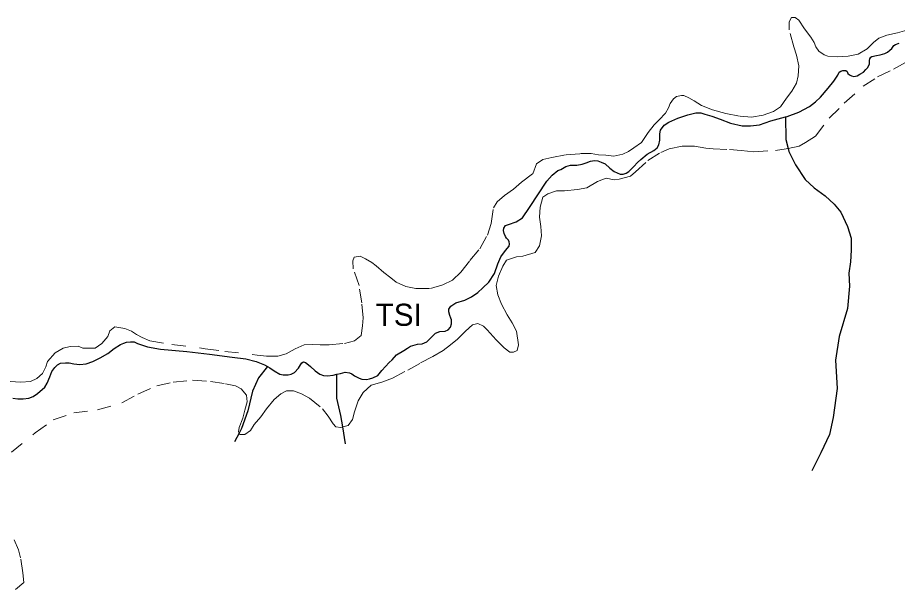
# Model space of a CAD drawing. Extents: x 391.8 to 446, y 8452 to 8507.5.
# Drawn here: x 420.22 to 426.58, y 8476.91 to 8481.04 of the extents above; entities that cross this region are included whole.
import ezdxf
from ezdxf.enums import TextEntityAlignment as Align

# ---------------------------------------------------------------- set-up
doc = ezdxf.new("R2010")
doc.units = 0
doc.header["$LTSCALE"] = 0.064
doc.linetypes.add('LONG_DASHED', pattern=[7.5, 6, -1.5])
doc.linetypes.add('SHORT_DASHED', pattern=[2.7, 1.5, -1.2])
for name, color, linetype, lineweight in [('21', 7, 'SHORT_DASHED', 13), ('63', 7, 'Continuous', 13), ('7', 7, 'Continuous', 25)]:
    doc.layers.add(name, color=color, linetype=linetype, lineweight=lineweight)
doc.layers.add('61', color=7, linetype='Continuous')

msp = doc.modelspace()

# ---------------------------------------------------------------- linework, layer by layer
at = {"layer": '21'}
for points in [[(420.9981, 8478.7971), (421.0479, 8478.7779), (421.0824, 8478.7549), (421.1246, 8478.732), (421.1783, 8478.709), (421.3393, 8478.6822), (421.5788, 8478.6516), (421.7206, 8478.6325), (421.9545, 8478.6057), (422.0235, 8478.598), (422.104, 8478.598), (422.1653, 8478.6133), (422.2305, 8478.6516), (422.2956, 8478.6784), (422.357, 8478.6822), (422.4106, 8478.6784), (422.4758, 8478.6784), (422.587, 8478.6899), (422.6598, 8478.709), (422.7058, 8478.7473), (422.7173, 8478.8162), (422.7211, 8478.8736), (422.7109, 8478.9827), (422.6918, 8479.1091), (422.6496, 8479.2277), (422.6458, 8479.2852), (422.6573, 8479.312), (422.6994, 8479.3196), (422.7378, 8479.3005), (422.7838, 8479.2737), (422.8144, 8479.2507), (422.8719, 8479.2009), (422.9218, 8479.1627), (422.9601, 8479.132), (423.0291, 8479.1014), (423.1019, 8479.0861), (423.2093, 8479.0861), (423.2974, 8479.1129), (423.3664, 8479.1473), (423.4277, 8479.2048), (423.4929, 8479.289), (423.5657, 8479.3732), (423.6194, 8479.4728), (423.6462, 8479.557), (423.6632, 8479.67), (423.69, 8479.7121), (423.7437, 8479.7581), (423.8088, 8479.804), (423.8663, 8479.8538), (423.9468, 8479.915), (423.9737, 8479.9878), (424.0197, 8480.0184), (424.0848, 8480.0337), (424.1883, 8480.0529), (424.2918, 8480.0605), (424.3685, 8480.0605), (424.4221, 8480.0529), (424.4758, 8480.049), (424.5333, 8480.0414), (424.5985, 8480.0567), (424.6406, 8480.0758), (424.679, 8480.1026), (424.7326, 8480.1409), (424.7825, 8480.2137), (424.8261, 8480.2693), (424.8606, 8480.3038), (424.9066, 8480.3536), (424.9296, 8480.3919), (424.9411, 8480.4225), (424.9641, 8480.4569), (424.9871, 8480.4722), (425.0216, 8480.4799), (425.0407, 8480.4799), (425.0752, 8480.4646), (425.1136, 8480.4416), (425.1672, 8480.4072), (425.2477, 8480.3765), (425.3436, 8480.3497), (425.4471, 8480.3306), (425.5276, 8480.3229), (425.6119, 8480.3383), (425.6886, 8480.3651), (425.7384, 8480.3995), (425.7806, 8480.4608), (425.8205, 8480.5111), (425.855, 8480.5685), (425.8665, 8480.6221), (425.8703, 8480.6949), (425.855, 8480.7714), (425.8358, 8480.8327), (425.8013, 8480.9552), (425.8013, 8481.0126), (425.8167, 8481.0432), (425.8435, 8481.0432), (425.8703, 8481.0241)], [(425.8703, 8481.0241), (425.9125, 8480.9628), (425.9585, 8480.9016), (425.9815, 8480.8633), (425.993, 8480.8327), (426.016, 8480.802), (426.0543, 8480.7752)], [(426.0543, 8480.7752), (426.0812, 8480.7638), (426.1501, 8480.7599), (426.2268, 8480.7638), (426.2996, 8480.7791), (426.3648, 8480.8174), (426.4108, 8480.8633), (426.4491, 8480.8939), (426.5066, 8480.9169), (426.5833, 8480.9322), (426.6523, 8480.9513)], [(425.9922, 8480.1878), (426.0907, 8480.3172), (426.1996, 8480.4259), (426.3369, 8480.5473), (426.4406, 8480.6146), (426.5546, 8480.6715), (426.6687, 8480.7336)], [(425.7933, 8480.0976), (425.873, 8480.1153), (425.9196, 8480.1412), (425.9922, 8480.1878)], [(422.5736, 8478.0861), (422.613, 8478.0979), (422.6441, 8478.1393), (422.6596, 8478.1963), (422.6856, 8478.274), (422.7218, 8478.3361), (422.7789, 8478.3878), (422.8566, 8478.4086), (422.9344, 8478.4396), (423.0432, 8478.4966), (423.1365, 8478.5483), (423.2247, 8478.5949), (423.3005, 8478.6376), (423.3523, 8478.6791), (423.4042, 8478.7205), (423.4612, 8478.7774), (423.513, 8478.824), (423.5493, 8478.8344), (423.5908, 8478.8137), (423.6167, 8478.7878), (423.6841, 8478.7153), (423.7411, 8478.6583), (423.7826, 8478.6273), (423.8085, 8478.6273), (423.8344, 8478.6376), (423.8448, 8478.6791), (423.8293, 8478.7774), (423.7982, 8478.8395), (423.7619, 8478.8965), (423.7204, 8478.9741), (423.6945, 8479.0414), (423.6841, 8479.1088), (423.6997, 8479.1761), (423.7308, 8479.2485), (423.7567, 8479.2899), (423.8293, 8479.3158), (423.8759, 8479.321), (423.964, 8479.3469), (423.9951, 8479.3935), (424.0107, 8479.466), (424.0055, 8479.5333), (423.9951, 8479.6006), (424.0003, 8479.673), (424.0211, 8479.7455), (424.0573, 8479.7714), (424.1195, 8479.7921), (424.1766, 8479.7921), (424.2699, 8479.8025), (424.3373, 8479.8128), (424.415, 8479.8594), (424.4785, 8479.8823), (424.5356, 8479.872), (424.5718, 8479.8772), (424.6548, 8479.8979), (424.6911, 8479.9289), (424.7792, 8480.0118), (424.8725, 8480.0687), (424.9347, 8480.0946), (425.028, 8480.1153), (425.1161, 8480.1153), (425.1991, 8480.0998), (425.2509, 8480.0946), (425.3702, 8480.0894), (425.4531, 8480.0843), (425.5464, 8480.0739)], [(425.5464, 8480.0739), (425.7019, 8480.0843), (425.7797, 8480.0946), (425.7933, 8480.0976)], [(420.7834, 8478.6554), (420.8333, 8478.6899), (420.8754, 8478.7396), (420.8908, 8478.7817), (420.9253, 8478.8085), (420.9559, 8478.8047), (420.9981, 8478.7971)], [(420.1701, 8478.4142), (420.2468, 8478.4104), (420.3158, 8478.4142), (420.3618, 8478.4372), (420.4039, 8478.4717), (420.4269, 8478.5214), (420.4384, 8478.5597), (420.4959, 8478.621), (420.5534, 8478.6554), (420.6033, 8478.6669), (420.6608, 8478.6707), (420.6953, 8478.6554), (420.7834, 8478.6554)], [(421.2289, 8478.3827), (421.3481, 8478.4086), (421.4881, 8478.4241), (421.6177, 8478.4137), (421.7266, 8478.3982), (421.7991, 8478.3827), (421.8406, 8478.362), (421.8769, 8478.3154), (421.8821, 8478.2688), (421.8665, 8478.2067), (421.851, 8478.1497), (421.825, 8478.0824), (421.8199, 8478.0513), (421.8244, 8478.0422)], [(420.3502, 8478.0436), (420.4798, 8478.1368), (420.6301, 8478.1886), (420.8012, 8478.2093), (420.9774, 8478.2611), (421.0915, 8478.3232), (421.2289, 8478.3827)], [(421.8244, 8478.0422), (421.8302, 8478.0306), (421.8665, 8478.0306), (421.908, 8478.0617), (421.9339, 8478.1031), (421.9806, 8478.1601), (422.022, 8478.217), (422.079, 8478.2843), (422.1257, 8478.3257), (422.1672, 8478.3464), (422.219, 8478.3464), (422.276, 8478.3257), (422.3331, 8478.2947), (422.4264, 8478.217), (422.4678, 8478.1652), (422.5041, 8478.1083), (422.5249, 8478.0876), (422.5611, 8478.0824), (422.5736, 8478.0861)], [(420.1791, 8477.9039), (420.3502, 8478.0436)], [(420.2086, 8476.9129), (420.2675, 8476.9622), (420.2604, 8477.032), (420.2449, 8477.1407), (420.2293, 8477.1976), (420.1982, 8477.2701)]]:
    msp.add_lwpolyline(points, dxfattribs=at)
at = {"layer": '63', "linetype": 'LONG_DASHED', "lineweight": 25}
for points in [[(425.7733, 8480.3259), (425.777, 8480.1624), (425.7933, 8480.0976)], [(425.7933, 8480.0976), (425.7985, 8480.0767), (425.8468, 8479.9802), (425.9165, 8479.873), (425.9809, 8479.8141), (426.0614, 8479.7552), (426.1258, 8479.6962), (426.1741, 8479.6373), (426.2224, 8479.5354), (426.2492, 8479.4497), (426.2492, 8479.364), (426.2438, 8479.2782), (426.2331, 8479.1978), (426.2381, 8479.1039), (426.222, 8478.9431), (426.163, 8478.7395), (426.1361, 8478.568), (426.1469, 8478.3644), (426.12, 8478.1554), (426.0932, 8478.0321), (426.0288, 8477.8982), (425.9644, 8477.7696)]]:
    msp.add_lwpolyline(points, dxfattribs=at)
at = {"layer": '7'}
msp.add_line((422.5937, 8477.9654), (422.5736, 8478.0861), dxfattribs=at)
for points in [[(425.7733, 8480.3259), (425.7857, 8480.3293), (425.8699, 8480.3612), (425.9473, 8480.4021), (425.9919, 8480.4346), (426.0284, 8480.4687), (426.083, 8480.5324), (426.1239, 8480.5846), (426.1535, 8480.6278), (426.1626, 8480.6483), (426.174, 8480.6574), (426.1899, 8480.6619), (426.2104, 8480.6619), (426.2195, 8480.6528), (426.2263, 8480.6392), (426.2377, 8480.6301), (426.2514, 8480.6233), (426.2696, 8480.6187), (426.2923, 8480.6233), (426.3128, 8480.6346), (426.3379, 8480.6483), (426.3561, 8480.6687), (426.3697, 8480.6824), (426.3811, 8480.7096), (426.3811, 8480.7324), (426.3834, 8480.746), (426.3902, 8480.7574), (426.3993, 8480.7619), (426.4334, 8480.7687), (426.4585, 8480.7733), (426.4926, 8480.7846), (426.5108, 8480.7937), (426.529, 8480.8074), (426.5427, 8480.821), (426.5586, 8480.8414), (426.57, 8480.8483), (426.5973, 8480.8574)], [(422.5313, 8478.4666), (422.558, 8478.4718), (422.5922, 8478.4809), (422.6218, 8478.4764), (422.64, 8478.4695), (422.6582, 8478.4559), (422.6923, 8478.4377), (422.7128, 8478.4309), (422.7446, 8478.4286), (422.7674, 8478.4332), (422.7924, 8478.44), (422.8266, 8478.4582), (422.8562, 8478.4945), (422.9085, 8478.5514), (422.9313, 8478.5718), (422.9631, 8478.6082), (423.0155, 8478.6377), (423.0428, 8478.6559), (423.0632, 8478.6696), (423.1133, 8478.6832), (423.1475, 8478.6877), (423.1816, 8478.7014), (423.1975, 8478.7173), (423.2248, 8478.7446), (423.2453, 8478.7627), (423.2749, 8478.7764), (423.3136, 8478.7786), (423.3369, 8478.7867), (423.3528, 8478.8072), (423.3597, 8478.8322), (423.3597, 8478.8594), (423.3551, 8478.8731), (423.3483, 8478.8912), (423.3415, 8478.9185), (423.3415, 8478.9367), (423.3551, 8478.9594), (423.3915, 8478.9822), (423.4553, 8479.0026), (423.5053, 8479.0253), (423.5508, 8479.0572), (423.5872, 8479.0913), (423.6305, 8479.1322), (423.6714, 8479.1958), (423.6942, 8479.264), (423.7175, 8479.3156), (423.7425, 8479.3519), (423.763, 8479.3746), (423.7767, 8479.3928), (423.779, 8479.4087), (423.7767, 8479.4246), (423.7721, 8479.436), (423.7585, 8479.4496), (423.7494, 8479.461), (423.7403, 8479.4837), (423.7357, 8479.5042), (423.738, 8479.5224), (423.7494, 8479.5406), (423.7721, 8479.5496), (423.8267, 8479.5678), (423.8723, 8479.5974), (423.9246, 8479.6724), (424.0498, 8479.861), (424.0889, 8479.9057), (424.1298, 8479.9398), (424.1503, 8479.9466), (424.1867, 8479.967), (424.2209, 8479.9784), (424.2664, 8479.9784), (424.3051, 8479.9852), (424.3347, 8479.9943), (424.3642, 8480.0057), (424.3938, 8480.0102), (424.4189, 8480.008), (424.4416, 8479.9989), (424.4712, 8479.9875), (424.5053, 8479.9557), (424.5349, 8479.9307), (424.5782, 8479.9125), (424.6009, 8479.9125), (424.6237, 8479.9193), (424.6419, 8479.9307), (424.6783, 8479.967), (424.7056, 8479.9966), (424.7284, 8480.0193), (424.7739, 8480.0557), (424.8217, 8480.083), (424.8467, 8480.1034), (424.8581, 8480.1239), (424.8649, 8480.158), (424.8672, 8480.2034), (424.8717, 8480.2307), (424.8968, 8480.2671), (424.9309, 8480.2875), (424.9969, 8480.3171), (425.0688, 8480.3407)], [(425.0688, 8480.3407), (425.1257, 8480.3543), (425.1621, 8480.3543), (425.1917, 8480.3453), (425.2418, 8480.3316), (425.301, 8480.3089), (425.3761, 8480.2816)], [(425.3761, 8480.2816), (425.4603, 8480.2612), (425.5217, 8480.2612), (425.5877, 8480.268), (425.6696, 8480.2975), (425.7733, 8480.3259)], [(420.1898, 8478.294), (420.2239, 8478.2894), (420.2626, 8478.2894), (420.3036, 8478.294), (420.3354, 8478.3053), (420.3673, 8478.3281), (420.4196, 8478.3735), (420.4378, 8478.4031), (420.4561, 8478.4485), (420.472, 8478.4872), (420.4925, 8478.5167), (420.5129, 8478.5349), (420.5334, 8478.5463), (420.5698, 8478.5485), (420.5971, 8478.5485), (420.629, 8478.5417), (420.6734, 8478.5365), (420.7189, 8478.5433), (420.7667, 8478.5592), (420.8191, 8478.5865), (420.8759, 8478.616), (420.9215, 8478.6524), (420.967, 8478.6819), (420.992, 8478.691), (421.0102, 8478.6978), (421.0398, 8478.7001), (421.0648, 8478.7001), (421.0899, 8478.6887), (421.1627, 8478.666), (421.256, 8478.6478), (421.4472, 8478.6319), (421.6117, 8478.6112), (421.7756, 8478.5908), (421.8734, 8478.5794), (421.9485, 8478.5589), (422.0077, 8478.5362), (422.0298, 8478.5232)], [(422.0298, 8478.5232), (421.9641, 8478.4422), (421.9219, 8478.3451), (421.8881, 8478.2017), (421.8416, 8478.0751), (421.8244, 8478.0422), (421.7909, 8477.978)], [(422.0298, 8478.5232), (422.0464, 8478.5135), (422.0782, 8478.4908), (422.1192, 8478.468), (422.1442, 8478.4635), (422.1784, 8478.4635), (422.2011, 8478.468), (422.2262, 8478.4794), (422.2535, 8478.5112), (422.2694, 8478.5362), (422.2785, 8478.5499), (422.2899, 8478.5567), (422.3035, 8478.5521), (422.3149, 8478.5453), (422.34, 8478.5226), (422.3741, 8478.4908), (422.4082, 8478.468), (422.4355, 8478.4589), (422.4628, 8478.4567), (422.5038, 8478.4612), (422.5313, 8478.4666)], [(422.5736, 8478.0861), (422.5599, 8478.1679), (422.5303, 8478.2945), (422.5303, 8478.3915), (422.5313, 8478.4666)]]:
    msp.add_lwpolyline(points, dxfattribs=at)

# ---------------------------------------------------------------- texts
at = {"layer": '61'}
msp.add_text('TSI', height=0.16, dxfattribs=at).set_placement((422.9785, 8478.8166), align=Align.CENTER)

doc.saveas('drawing.dxf')
